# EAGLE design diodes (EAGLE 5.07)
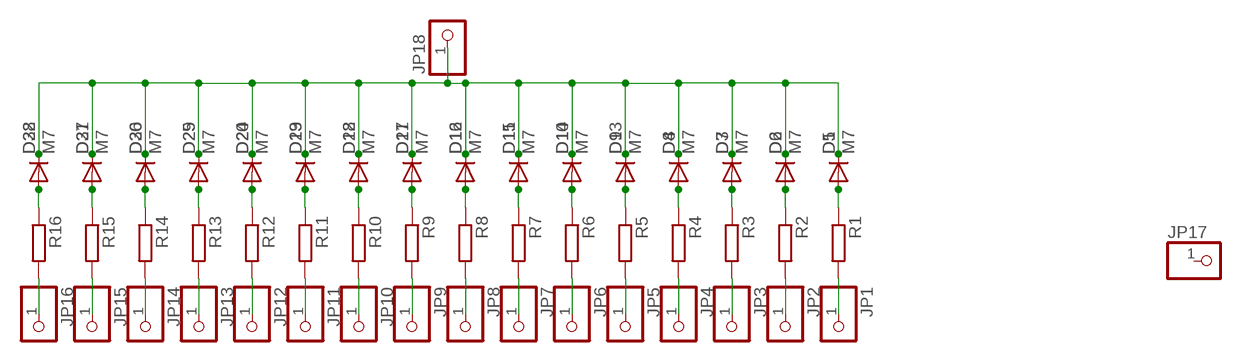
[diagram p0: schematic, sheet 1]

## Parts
D1  M7  1N4004DO41-10  [DO41-10]
D2  M7  1N4004DO41-10  [DO41-10]
D3  M7  1N4004DO41-10  [DO41-10]
D4  M7  1N4004DO41-10  [DO41-10]
D5  DIODE-SMA-DO214  [SMA-DO214AC]
D6  DIODE-SMA-DO214  [SMA-DO214AC]
D7  DIODE-SMA-DO214  [SMA-DO214AC]
D8  DIODE-SMA-DO214  [SMA-DO214AC]
D9  M7  1N4004DO41-10  [DO41-10]
D10  M7  1N4004DO41-10  [DO41-10]
D11  M7  1N4004DO41-10  [DO41-10]
D12  M7  1N4004DO41-10  [DO41-10]
D13  DIODE-SMA-DO214  [SMA-DO214AC]
D14  DIODE-SMA-DO214  [SMA-DO214AC]
D15  DIODE-SMA-DO214  [SMA-DO214AC]
D16  DIODE-SMA-DO214  [SMA-DO214AC]
D17  M7  1N4004DO41-10  [DO41-10]
D18  M7  1N4004DO41-10  [DO41-10]
D19  M7  1N4004DO41-10  [DO41-10]
D20  M7  1N4004DO41-10  [DO41-10]
D21  DIODE-SMA-DO214  [SMA-DO214AC]
D22  DIODE-SMA-DO214  [SMA-DO214AC]
D23  DIODE-SMA-DO214  [SMA-DO214AC]
D24  DIODE-SMA-DO214  [SMA-DO214AC]
D25  M7  1N4004DO41-10  [DO41-10]
D26  M7  1N4004DO41-10  [DO41-10]
D27  M7  1N4004DO41-10  [DO41-10]
D28  M7  1N4004DO41-10  [DO41-10]
D29  DIODE-SMA-DO214  [SMA-DO214AC]
D30  DIODE-SMA-DO214  [SMA-DO214AC]
D31  DIODE-SMA-DO214  [SMA-DO214AC]
D32  DIODE-SMA-DO214  [SMA-DO214AC]
JP1  PINHD-1X11MM0  [1X1MM0]
JP2  PINHD-1X11MM0  [1X1MM0]
JP3  PINHD-1X11MM0  [1X1MM0]
JP4  PINHD-1X11MM0  [1X1MM0]
JP5  PINHD-1X11MM0  [1X1MM0]
JP6  PINHD-1X11MM0  [1X1MM0]
JP7  PINHD-1X11MM0  [1X1MM0]
JP8  PINHD-1X11MM0  [1X1MM0]
JP9  PINHD-1X11MM0  [1X1MM0]
JP10  PINHD-1X11MM0  [1X1MM0]
JP11  PINHD-1X11MM0  [1X1MM0]
JP12  PINHD-1X11MM0  [1X1MM0]
JP13  PINHD-1X11MM0  [1X1MM0]
JP14  PINHD-1X11MM0  [1X1MM0]
JP15  PINHD-1X11MM0  [1X1MM0]
JP16  PINHD-1X11MM0  [1X1MM0]
JP17  PINHD-1X14.5MM  [1X4MM5]
JP18  PINHD-1X11MM6  [1X1MM8]
R1  R-EU_R2010  [R2010]
R2  R-EU_R2010  [R2010]
R3  R-EU_R2010  [R2010]
R4  R-EU_R2010  [R2010]
R5  R-EU_R2010  [R2010]
R6  R-EU_R2010  [R2010]
R7  R-EU_R2010  [R2010]
R8  R-EU_R2010  [R2010]
R9  R-EU_R2010  [R2010]
R10  R-EU_R2010  [R2010]
R11  R-EU_R2010  [R2010]
R12  R-EU_R2010  [R2010]
R13  R-EU_R2010  [R2010]
R14  R-EU_R2010  [R2010]
R15  R-EU_R2010  [R2010]
R16  R-EU_R2010  [R2010]

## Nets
MINUS: D1.C D2.C D3.C D4.C D5.K(C) D6.K(C) D7.K(C) D8.K(C) D9.C D10.C D11.C D12.C D13.K(C) D14.K(C) D15.K(C) D16.K(C) D17.C D18.C D19.C D20.C D21.K(C) D22.K(C) D23.K(C) D24.K(C) D25.C D26.C D27.C D28.C D29.K(C) D30.K(C) D31.K(C) D32.K(C) JP18.1
N$1: JP1.1 R1.2
N$2: D1.A D5.A R1.1
N$3: JP2.1 R2.2
N$4: D2.A D6.A R2.1
N$5: JP3.1 R3.2
N$6: D3.A D7.A R3.1
N$7: JP4.1 R4.2
N$8: D4.A D8.A R4.1
N$10: JP5.1 R5.2
N$11: D9.A D13.A R5.1
N$12: JP6.1 R6.2
N$13: D10.A D14.A R6.1
N$14: JP7.1 R7.2
N$15: D11.A D15.A R7.1
N$16: JP8.1 R8.2
N$17: D12.A D16.A R8.1
N$19: JP9.1 R9.2
N$20: D17.A D21.A R9.1
N$21: JP10.1 R10.2
N$22: D18.A D22.A R10.1
N$23: JP11.1 R11.2
N$24: D19.A D23.A R11.1
N$25: JP12.1 R12.2
N$26: D20.A D24.A R12.1
N$27: JP13.1 R13.2
N$28: D25.A D29.A R13.1
N$29: JP14.1 R14.2
N$30: D26.A D30.A R14.1
N$31: JP15.1 R15.2
N$32: D27.A D31.A R15.1
N$33: JP16.1 R16.2
N$34: D28.A D32.A R16.1
Unconnected: JP17.1

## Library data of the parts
D1-D4 D9-D12 D17-D20 D25-D28 = diode:1N4004: DIODE
D5-D8 D13-D16 D21-D24 D29-D32 = diode:DIODE-: DIODE
JP1-JP18 = pinhead:PINHD-1X1: PIN HEADER
R1-R16 = rcl:R-EU_: RESISTOR, European symbol

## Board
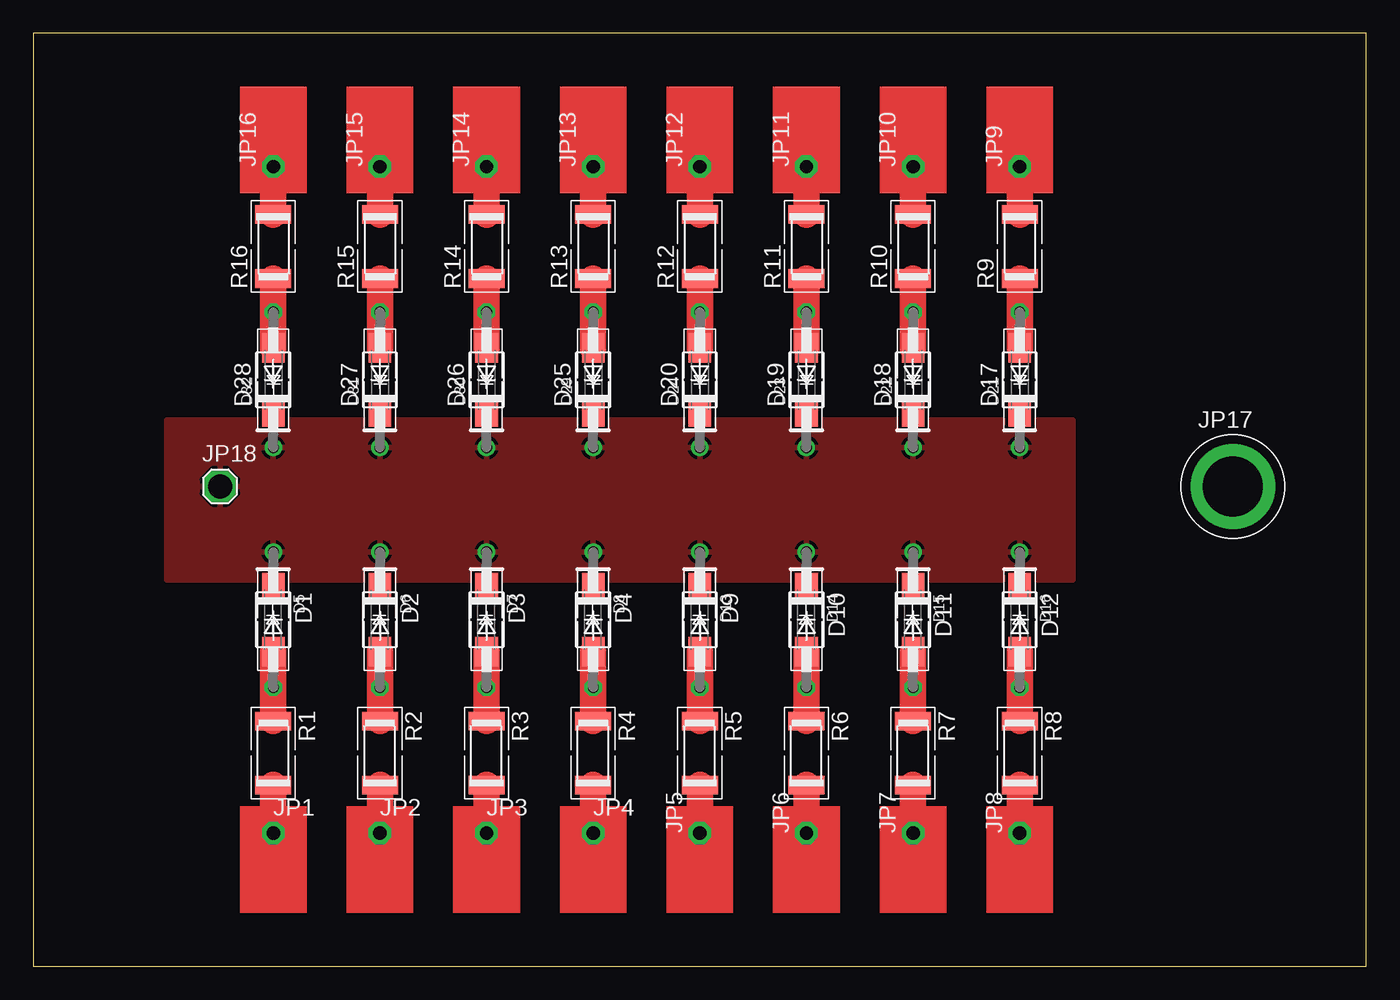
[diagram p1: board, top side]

Size 100 x 70 mm. Coordinates in mm from the lower left corner, seen from the top.
Outline: 0,0 100,0 100,70 0,70 0,0
Copper layers (1*16): Top 0.035mm / dielectric 1.5mm / Bottom 0.035mm
Design rules "default *": minimum track width 10mil, minimum drill 20mil, track to track 8mil, track to pad 8mil, pad to pad 8mil, via to via 8mil, smd to smd 8mil, copper to edge 40mil, drill to drill 8mil, minimum pad ring 10mil, minimum via ring 8mil, stop-mask expansion 4mil, vias tented up to drill 0mil, thermal gap 10mil

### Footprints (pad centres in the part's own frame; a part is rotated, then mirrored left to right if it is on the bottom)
DO41-10 = drill 0.8 octagon: A 5.08,0 | drill 0.8 round: C -5.08,0
SMA-DO214AC = smd 2.2 x 1.7: A 2.4,0; K -2.4,0
1X1MM0 = drill 1 pad 1.676 octagon: 1 0,0
1X4MM5 = drill 4.5 pad 6.35 round: 1 0,0
1X1MM8 = drill 1.8 pad 2.54 octagon: 1 0,0
R2010 = smd 1.4 x 2.7: 1 -2.4,0; 2 2.4,0

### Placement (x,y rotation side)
D1  18,26 270 top
D2  26,26 270 top
D3  34,26 270 top
D4  42,26 270 top
D5  18,26 270 top
D6  26,26 270 top
D7  34,26 270 top
D8  42,26 270 top
D9  50,26 270 top
D10  58,26 270 top
D11  66,26 270 top
D12  74,26 270 top
D13  50,26 270 top
D14  58,26 270 top
D15  66,26 270 top
D16  74,26 270 top
D17  74,44 90 top
D18  66,44 90 top
D19  58,44 90 top
D20  50,44 90 top
D21  74,44 90 top
D22  66,44 90 top
D23  58,44 90 top
D24  50,44 90 top
D25  42,44 90 top
D26  34,44 90 top
D27  26,44 90 top
D28  18,44 90 top
D29  42,44 90 top
D30  34,44 90 top
D31  26,44 90 top
D32  18,44 90 top
JP1  18,10 0 top
JP2  26,10 0 top
JP3  34,10 0 top
JP4  42,10 0 top
JP5  50,10 90 top
JP6  58,10 90 top
JP7  66,10 90 top
JP8  74,10 90 top
JP9  74,60 90 top
JP10  66,60 90 top
JP11  58,60 90 top
JP12  50,60 90 top
JP13  42,60 90 top
JP14  34,60 90 top
JP15  26,60 90 top
JP16  18,60 90 top
JP17  90,36 0 top
JP18  14,36 0 top
R1  18,16 270 top
R2  26,16 270 top
R3  34,16 270 top
R4  42,16 270 top
R5  50,16 270 top
R6  58,16 270 top
R7  66,16 270 top
R8  74,16 270 top
R9  74,54 90 top
R10  66,54 90 top
R11  58,54 90 top
R12  50,54 90 top
R13  42,54 90 top
R14  34,54 90 top
R15  26,54 90 top
R16  18,54 90 top

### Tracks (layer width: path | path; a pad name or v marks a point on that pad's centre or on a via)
MINUS
  pour Top: 10,41 78,41 78,29 10,29
N$1
  Top 2: JP1.1 R1.2
N$2
  Top 2: R1.1 D1.A D5.A
N$3
  Top 2: JP2.1 R2.2
N$4
  Top 2: R2.1 D2.A D6.A
N$5
  Top 2: JP3.1 R3.2
N$6
  Top 2: R3.1 D3.A D7.A
N$7
  Top 2: JP4.1 R4.2
N$8
  Top 2: R4.1 D4.A D8.A
N$10
  Top 2: JP5.1 R5.2
N$11
  Top 2: R5.1 D9.A D13.A
N$12
  Top 2: JP6.1 R6.2
N$13
  Top 2: R6.1 D10.A D14.A
N$14
  Top 2: JP7.1 R7.2
N$15
  Top 2: R7.1 D11.A D15.A
N$16
  Top 2: JP8.1 R8.2
N$17
  Top 2: R8.1 D12.A D16.A
N$19
  Top 2: R9.2 JP9.1
N$20
  Top 2: R9.1 D17.A D21.A
N$21
  Top 2: R10.2 JP10.1
N$22
  Top 2: D22.A D18.A R10.1
N$23
  Top 2: R11.2 JP11.1
N$24
  Top 2: D23.A D19.A R11.1
N$25
  Top 2: R12.2 JP12.1
N$26
  Top 2: R12.1 50,50 D20.A D24.A
N$27
  Top 2: R13.2 JP13.1
N$28
  Top 2: R13.1 D25.A D29.A
N$29
  Top 2: R14.2 JP14.1
N$30
  Top 2: R14.1 D26.A D30.A
N$31
  Top 2: R15.2 JP15.1
N$32
  Top 2: R15.1 D27.A D31.A
N$33
  Top 2: R16.2 JP16.1
N$34
  Top 2: R16.1 D28.A D32.A
(copper drawn outside any net)
  shapes: Top area x16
